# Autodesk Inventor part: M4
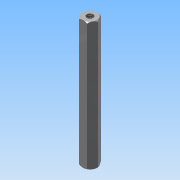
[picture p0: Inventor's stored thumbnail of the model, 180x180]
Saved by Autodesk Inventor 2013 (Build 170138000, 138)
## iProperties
Created: 2012-08
Part Number: M4
Material: Stahl
Document SubType Name: Modeling
Designer: rYan
Density: 7.85 g/cm^3
Mass: 17.4304 g
Surface Area: 23.0082 cm^2
Volume: 2.22043 cm^3
Author: rYan
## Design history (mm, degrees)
derived "Abstandsbolzen Typ A.ipt"
feature "Volumenkörper1::Abstandsbolzen Typ A.ipt"
tag "Bezeichnung1"
node "Volumenkörper1"
other parameters: "SW" = 7, "L" = 65, "d2" = 0, "d16" = 45 deg
